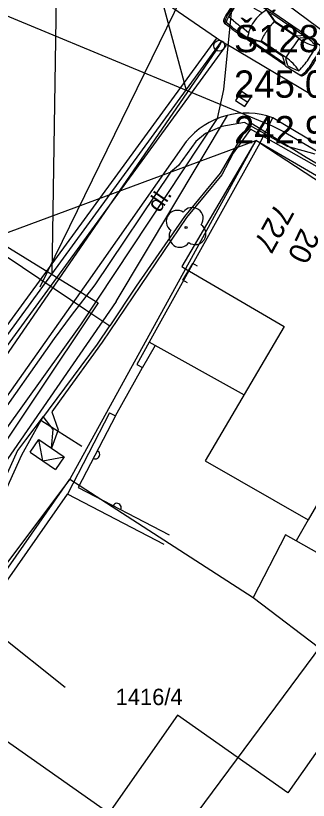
# Model space of a CAD drawing. Extents: x -601580 to 4, y -1204314 to 4.
# Drawn here: x -600325.47 to -600312.05, y -1203714.84 to -1203678.86 of the extents above; entities that cross this region are included whole.
import ezdxf

# ---------------------------------------------------------------- set-up
doc = ezdxf.new("R2010")
doc.units = 0
for name, color, linetype in [('00-EON NN', 7, 'Continuous'), ('00-EON VN', 7, 'Continuous'), ('00-INNOGY-NTL', 7, 'Continuous'), ('00-KN-HRANICE PARCEL', 7, 'Continuous'), ('00-KN-PARC. CISLA', 7, 'Continuous'), ('00-KN-VNITRNI KRESBA', 7, 'Continuous'), ('00-POLOHOPIS', 7, 'Continuous'), ('00-RAZÍTKO', 7, 'Continuous'), ('00-SITE KOM. KABEL', 7, 'Continuous'), ('00-VAK-KANAL-POPIS', 7, 'Continuous'), ('00-VAK-KANAL-POTRUBI', 7, 'Continuous'), ('00-VAK-VODA-RAD IGIS', 7, 'Continuous'), ('00-VODOVOD STAVAJICI', 7, 'Continuous'), ('11-REKONSTRUKCE  VYKOP', 7, 'Continuous'), ('11-REKONSTRUKCE VODOVOD', 7, 'Continuous'), ('11-REKONSTRUKCE VODOVOD POPIS', 7, 'Continuous'), ('1NP -vybaveni', 7, 'Continuous'), ('Vrstva 22', 7, 'Continuous'), ('Vrstva 26', 7, 'Continuous'), ('Vrstva 27', 7, 'Continuous'), ('Vrstva 28', 7, 'Continuous'), ('Vrstva 40', 7, 'Continuous'), ('Vrstva 6', 7, 'Continuous'), ('Vrstva 9', 7, 'Continuous')]:
    doc.layers.add(name, color=color, linetype=linetype)

# ---------------------------------------------------------------- blocks, each defined once
blk = doc.blocks.new('3.13_358')
at = {"layer": 'Vrstva 22'}
blk.add_circle((0, 0), 0.05, dxfattribs=at)
for centre, start, end in [((0, 0.5), 359.9999, 179.9999), ((-0.5, 0), 89.9999, 269.9999), ((0.5, 0), 269.9999, 89.9999), ((0, -0.5), 179.9999, 359.9999)]:
    blk.add_arc(centre, 0.5, start, end, dxfattribs=at)
blk = doc.blocks.new('6.30_262')
at = {"layer": 'Vrstva 27'}
blk.add_line((-0.25, 0), (0.25, 0), dxfattribs=at)
blk.add_lwpolyline([(-0.25, -0.25), (0.25, -0.25), (0.25, 0.25), (-0.25, 0.25)], close=True, dxfattribs=at)
blk = doc.blocks.new('6.14A_572')
at = {"layer": 'Vrstva 28'}
blk.add_circle((0, 0), 0.25, dxfattribs=at)
blk = doc.blocks.new('DL_32')
at = {"layer": 'Vrstva 40'}
blk.add_text('dl.', height=0.75, rotation=360, dxfattribs=at).set_placement((-0.174, -0.375))
blk = doc.blocks.new('VCHOD_2442')
at = {"layer": 'Vrstva 6'}
blk.add_line((0, 0.25), (0, 0), dxfattribs=at)
blk = doc.blocks.new('VCHOD_2444')
at = {"layer": 'Vrstva 6'}
blk.add_line((0, 0.25), (0, 0), dxfattribs=at)
blk = doc.blocks.new('NN630')
at = {"layer": 'Vrstva 9'}
for points in [[(-3, -700), (-703, 0)], [(-703, -700), (-703, 0), (697, 0), (697, -700)], [(-3, -700), (697, 0)], [(-703, -700), (697, -700)]]:
    blk.add_lwpolyline(points, dxfattribs=at)
blk = doc.blocks.new('CA0106H2')
for p, q in [((1.038, 0), (1.038, -0.039)), ((1.038, 0), (2.851, 0)), ((1.95, -0.07), (1.95, 0)), ((2.824, 0.153), (2.878, -0.152)), ((2.874, 0.137), (2.824, 0.153)), ((2.967, -0.12), (2.874, 0.137)), ((2.924, 0), (3.528, 0)), ((0.538, -0.013), (0.17, -0.031)), ((0.902, -0.068), (1.15, -0.271)), ((1.038, -0.039), (1.336, -0.284)), ((2.863, -0.07), (1.075, -0.07)), ((1.197, -0.322), (2.562, -0.322)), ((1.336, -0.284), (2.512, -0.284)), ((2.512, -0.284), (3.106, -0.07)), ((2.558, -0.284), (3.152, -0.07)), ((3.106, -0.07), (2.949, -0.07)), ((3.152, -0.07), (3.533, -0.07)), ((3.245, -0.3), (3.626, -0.321)), ((4.028, -0.013), (4.396, -0.031)), ((4.033, -0.083), (4.364, -0.099)), ((0, -0.848), (0, -0.496)), ((1.194, -0.364), (1.194, -0.848)), ((4.124, -0.362), (4.427, -0.394)), ((4.432, -0.848), (4.432, -0.508)), ((4.57, -0.848), (4.57, -0.508)), ((0, -0.848), (0, -1.199)), ((1.194, -1.331), (1.194, -0.848)), ((4.432, -0.848), (4.432, -1.187)), ((4.57, -0.848), (4.57, -1.187)), ((0.902, -1.627), (1.15, -1.424)), ((1.038, -1.656), (1.336, -1.411)), ((1.197, -1.373), (2.562, -1.373)), ((1.336, -1.411), (2.512, -1.411)), ((2.512, -1.411), (3.106, -1.625)), ((2.558, -1.411), (3.152, -1.625)), ((3.245, -1.395), (3.626, -1.374)), ((4.124, -1.333), (4.427, -1.301)), ((0.538, -1.682), (0.17, -1.664)), ((1.038, -1.695), (1.038, -1.656)), ((1.038, -1.695), (2.851, -1.695)), ((2.863, -1.625), (1.075, -1.625)), ((1.95, -1.625), (1.95, -1.695)), ((2.824, -1.848), (2.878, -1.543)), ((2.967, -1.575), (2.874, -1.832)), ((2.924, -1.695), (3.528, -1.695)), ((3.106, -1.625), (2.949, -1.625)), ((3.152, -1.625), (3.533, -1.625)), ((4.028, -1.682), (4.396, -1.664)), ((4.033, -1.612), (4.364, -1.596)), ((2.874, -1.832), (2.824, -1.848))]:
    blk.add_line(p, q)
for points in [[(0.064, -0.848), (0.064, -0.505)], [(4.508, -0.848), (4.508, -0.508)], [(0.064, -0.848), (0.064, -1.19)], [(4.508, -0.848), (4.508, -1.187)]]:
    blk.add_lwpolyline(points)
for centre, radius, start, end in [((1.038, -10), 10, 90, 92.8655), ((3.528, -10), 10, 87.1345, 90), ((1.215, -0.496), 1.215, 161.5481, 180), ((0.176, -0.151), 0.12, 92.8655, 160.933), ((1.279, -0.505), 1.215, 161.5481, 180), ((0.257, -0.164), 0.138, 89.0794, 161.5481), ((4.17, -0.848), 3.876, 169.8074, 180), ((1.081, -2.75), 2.689, 93.8081, 105.6622), ((1.18, 1.875), 2.197, 247.9492, 270.4514), ((1.074, -0.364), 0.12, 0, 50.6237), ((2.784, -0.284), 0.888, 166.0463, 180), ((2.812, -0.284), 0.888, 166.0463, 180), ((2.858, -0.352), 0.909, 161.9013, 175.6916), ((-1.274, -0.848), 3.876, 360, 8.3716), ((1.563, -0.848), 1.769, 0, 26.07), ((3.533, -10.07), 10, 87.1345, 90), ((3.066, -10.306), 10, 83.9233, 86.7888), ((4.315, -0.167), 0.138, 18.4519, 90.9206), ((4.484, -0.087), 0.12, 158.1675, 197.8029), ((3.217, -0.508), 1.215, 0, 18.4519), ((4.39, -0.151), 0.12, 19.067, 87.1345), ((3.293, -0.508), 1.215, 0, 18.4519), ((3.355, -0.508), 1.215, 0, 19.067), ((4.17, -0.848), 3.876, 180, 190.1926), ((-1.274, -0.848), 3.876, 351.6284, 0), ((1.563, -0.848), 1.769, 333.93, 0), ((1.215, -1.199), 1.215, 180, 198.4519), ((1.279, -1.19), 1.215, 180, 198.4519), ((1.18, -3.57), 2.197, 89.5486, 112.0508), ((1.074, -1.331), 0.12, 309.3763, 0), ((2.784, -1.411), 0.888, 180, 193.9537), ((2.812, -1.411), 0.888, 180, 193.9537), ((2.858, -1.343), 0.909, 184.3084, 198.0987), ((3.066, 8.611), 10, 273.2112, 276.0767), ((3.217, -1.187), 1.215, 341.5481, 0), ((3.293, -1.187), 1.215, 341.5481, 0), ((3.355, -1.187), 1.215, 340.933, 0), ((0.176, -1.544), 0.12, 199.067, 267.1345), ((0.257, -1.531), 0.138, 198.4519, 270.9206), ((1.081, 1.055), 2.689, 254.3378, 266.1919), ((1.038, 8.305), 10, 267.1345, 270), ((3.528, 8.305), 10, 270, 272.8655), ((3.533, 8.375), 10, 270, 272.8655), ((4.315, -1.528), 0.138, 269.0794, 341.5481), ((4.484, -1.608), 0.12, 162.1971, 201.8325), ((4.39, -1.544), 0.12, 272.8655, 340.933)]:
    blk.add_arc(centre, radius, start, end)

msp = doc.modelspace()

# ---------------------------------------------------------------- linework, layer by layer
at = {"layer": '00-EON NN'}
for points in [[(-600300.1, -1203693.14), (-600300.09, -1203692.82), (-600302.356, -1203691.251), (-600303.624, -1203690.511), (-600305.35, -1203689.5), (-600311.54, -1203685.86), (-600314.7, -1203684.06), (-600315.49, -1203685.17), (-600316.007, -1203686.155), (-600317.63, -1203688.11), (-600321.5, -1203693.84), (-600323.385, -1203696.438)], [(-600323.385, -1203696.438), (-600323.817, -1203697.034), (-600323.521, -1203697.85), (-600323.824, -1203698.698), (-600323.753, -1203697.835), (-600324.207, -1203697.234), (-600325.017, -1203698.307)], [(-600325.017, -1203698.307), (-600325.386, -1203698.796), (-600326.82, -1203701.97), (-600328.814, -1203704.512), (-600330.617, -1203706.864), (-600331.49, -1203707.646), (-600333.526, -1203710.518), (-600334.519, -1203712.072), (-600336.22, -1203714.37), (-600337.32, -1203716)]]:
    msp.add_lwpolyline(points, dxfattribs=at)
at = {"layer": '00-EON VN'}
for points in [[(-600352.702, -1203647.788), (-600344.954, -1203653.759), (-600330.827, -1203664.425), (-600321.645, -1203670.963), (-600317.713, -1203673.458), (-600315.791, -1203674.896), (-600315.293, -1203675.777), (-600315.944, -1203682.246), (-600316.226, -1203683.581), (-600322.501, -1203693.042), (-600331.079, -1203704.985), (-600348.911, -1203730.288), (-600354.208, -1203737.743), (-600361.516, -1203748.136), (-600365.138, -1203753.003), (-600368.824, -1203758.254), (-600375.091, -1203769.039), (-600381.398, -1203780.278), (-600382.49, -1203782.6), (-600383.25, -1203783.59)], [(-600311.727, -1203685.219), (-600313.007, -1203684.869), (-600314.967, -1203683.759), (-600316.007, -1203683.949), (-600316.757, -1203684.269), (-600317.207, -1203684.639), (-600317.997, -1203685.729), (-600318.367, -1203686.039), (-600321.837, -1203691.209), (-600322.927, -1203692.609), (-600323.707, -1203693.669), (-600326.587, -1203697.729), (-600333.047, -1203707.069), (-600337.327, -1203713.329), (-600344.497, -1203723.269)]]:
    msp.add_lwpolyline(points, dxfattribs=at)
at = {"layer": '00-INNOGY-NTL'}
for points in [[(-600309.24, -1203678.67), (-600322.08, -1203669.74), (-600324.1, -1203669.99), (-600324.38, -1203670.02), (-600324.57, -1203670.3), (-600329.11, -1203676.87), (-600329.27, -1203677.14), (-600328.72, -1203677.64), (-600328.46, -1203677.78), (-600313.71, -1203683.92), (-600313.19, -1203684.18), (-600311.2, -1203685.34)], [(-600331.63, -1203676.31), (-600333.84, -1203679.52), (-600334.07, -1203679.86), (-600334.63, -1203680.67), (-600332.29, -1203684.08), (-600331.07, -1203685.85), (-600329.31, -1203687.34), (-600321.69, -1203692.03)], [(-600321.69, -1203692.03), (-600330.58, -1203705.33), (-600337.06, -1203714.26), (-600337.47, -1203714.88), (-600341.61, -1203721.03), (-600343.93, -1203724.48), (-600344.29, -1203725.01), (-600352.8, -1203737.19), (-600355.42, -1203740.94), (-600356.36, -1203742.04), (-600356.56, -1203742.28), (-600357.37, -1203743.06), (-600358.82, -1203744.14), (-600359.04, -1203744.31), (-600359.16, -1203744.4), (-600365.08, -1203752.77), (-600365.18, -1203752.95), (-600368.57, -1203759.1), (-600375.05, -1203770.85), (-600375.18, -1203771.08)]]:
    msp.add_lwpolyline(points, dxfattribs=at)
at = {"layer": '00-KN-HRANICE PARCEL'}
for p, q in [((-600305.11, -1203690.04), (-600314.45, -1203684.58)), ((-600322.98, -1203700.12), (-600331.6, -1203711.54)), ((-600322.98, -1203700.12), (-600314.57, -1203705.54)), ((-600314.57, -1203705.54), (-600309.44, -1203709.45))]:
    msp.add_line(p, q, dxfattribs=at)
for points in [[(-600337.24, -1203696.89), (-600330.06, -1203690.37), (-600314.45, -1203684.58)], [(-600314.45, -1203684.58), (-600317.68, -1203690.47), (-600322.98, -1203700.12)], [(-600305.11, -1203690.04), (-600309.03, -1203696.78), (-600312.05, -1203701.98), (-600312.6, -1203702.94), (-600313.09, -1203702.67), (-600314.57, -1203705.54)], [(-600309.44, -1203709.45), (-600312.98, -1203714.49), (-600318.05, -1203710.93), (-600321.19, -1203715.42), (-600329.58, -1203709.54), (-600322.98, -1203700.12)]]:
    msp.add_lwpolyline(points, dxfattribs=at)
at = {"layer": '00-KN-VNITRNI KRESBA'}
for p, q in [((-600314.45, -1203684.58), (-600317.85, -1203690.37)), ((-600317.85, -1203690.37), (-600317.68, -1203690.47)), ((-600317.68, -1203690.47), (-600313.15, -1203693.12)), ((-600313.15, -1203693.12), (-600316.78, -1203699.27)), ((-600316.78, -1203699.27), (-600312.05, -1203701.98)), ((-600310.53, -1203704.12), (-600312.6, -1203702.94))]:
    msp.add_line(p, q, dxfattribs=at)
at = {"layer": '00-POLOHOPIS'}
for p, q in [((-600320.865, -1203691.972), (-600315.749, -1203683.433)), ((-600314.269, -1203684.712), (-600313.676, -1203683.546)), ((-600304.426, -1203689.116), (-600313.676, -1203683.546)), ((-600317.651, -1203684.638), (-600322.148, -1203691.029)), ((-600317.805, -1203690.988), (-600317.344, -1203690.225)), ((-600322.148, -1203691.029), (-600335.017, -1203709.24)), ((-600320.865, -1203691.972), (-600333.392, -1203710.107)), ((-600319.34, -1203693.831), (-600319.918, -1203694.853)), ((-600319.078, -1203693.978), (-600319.656, -1203695)), ((-600314.97, -1203696.261), (-600319.34, -1203693.831)), ((-600320.893, -1203697.211), (-600319.656, -1203695)), ((-600319.918, -1203694.853), (-600319.656, -1203695)), ((-600321.16, -1203697.073), (-600323.1, -1203700.803)), ((-600320.893, -1203697.211), (-600322.602, -1203700.498)), ((-600321.16, -1203697.073), (-600320.893, -1203697.211)), ((-600322.602, -1203700.498), (-600318.433, -1203702.666)), ((-600327.117, -1203706.554), (-600323.1, -1203700.803)), ((-600318.664, -1203703.11), (-600323.1, -1203700.803)), ((-600323.204, -1203709.666), (-600327.117, -1203706.554))]:
    msp.add_line(p, q, dxfattribs=at)
for points in [[(-600307.904, -1203694.856), (-600305.164, -1203690.673), (-600314.269, -1203684.712), (-600319.34, -1203693.831)], [(-600320.893, -1203697.211), (-600322.602, -1203700.498)], [(-600322.602, -1203700.498), (-600318.433, -1203702.666)]]:
    msp.add_lwpolyline(points, dxfattribs=at)
for centre, radius, start, end in [((-600314.897, -1203686.881), 3.551, 69.885, 140.8373), ((-600321.816, -1203698.985), 0.2, 242.5274, 62.5303), ((-600320.828, -1203701.421), 0.2, 332.5228, 152.5257)]:
    msp.add_arc(centre, radius, start, end, dxfattribs=at)
at = {"layer": '00-RAZÍTKO'}
msp.add_lwpolyline([(-600188.969, -1203708.417), (-600246.123, -1203785.417), (-600325.417, -1203726.559), (-600268.263, -1203649.56)], close=True, dxfattribs=at)
at = {"layer": '00-SITE KOM. KABEL'}
for points in [[(-600291.91, -1203697.34), (-600294.89, -1203695.51), (-600296.18, -1203694.98), (-600299.85, -1203692.83), (-600301.61, -1203691.58), (-600303.13, -1203690.66), (-600304.86, -1203689.65), (-600306.01, -1203688.96), (-600312.14, -1203685.36), (-600314.73, -1203683.76), (-600316.09, -1203686.08)], [(-600316.09, -1203686.08), (-600317.72, -1203688.07), (-600319.94, -1203691.26), (-600321.15, -1203693.08)], [(-600329.66, -1203687.89), (-600328.78, -1203687.96), (-600322.25, -1203692.35), (-600321.15, -1203693.08)], [(-600328.78, -1203687.96), (-600322.25, -1203692.35)], [(-600324.32, -1203697.42), (-600321.71, -1203693.92), (-600321.15, -1203693.08)], [(-600324.32, -1203697.42), (-600325.2, -1203699.01), (-600326.63, -1203702.13)], [(-600322.43, -1203698.61), (-600324.32, -1203697.42)]]:
    msp.add_lwpolyline(points, dxfattribs=at)
at = {"layer": '00-VAK-KANAL-POTRUBI'}
msp.add_line((-600356.108, -1203646.172), (-600311.102, -1203679.776), dxfattribs=at)
at = {"layer": '00-VAK-VODA-RAD IGIS'}
for points in [[(-600316.256, -1203679.894), (-600332.434, -1203668.792), (-600354.837, -1203651.734), (-600377.846, -1203634.299)], [(-600316.022, -1203680.054), (-600316.256, -1203679.894)], [(-600316.022, -1203680.054), (-600316.133, -1203680.243)], [(-600315.791, -1203680.191), (-600316.022, -1203680.054)], [(-600236.89, -1203728.365), (-600242.377, -1203724.953), (-600264, -1203711.729), (-600288.949, -1203696.473), (-600297.916, -1203690.812), (-600315.791, -1203680.191)]]:
    msp.add_lwpolyline(points, dxfattribs=at)
at = {"layer": '00-VODOVOD STAVAJICI'}
msp.add_lwpolyline([(-600316.133, -1203680.243), (-600330.382, -1203700.926)], dxfattribs=at)
at = {"layer": '11-REKONSTRUKCE  VYKOP'}
for points in [[(-600335.828, -1203706.693), (-600316.248, -1203679.889)], [(-600336.078, -1203707.985), (-600315.796, -1203680.219)]]:
    msp.add_lwpolyline(points, dxfattribs=at)
at = {"layer": '11-REKONSTRUKCE VODOVOD'}
msp.add_lwpolyline([(-600336.304, -1203707.82), (-600316.022, -1203680.054)], dxfattribs=at)
msp.add_lwpolyline([(-600336.304, -1203707.82), (-600316.022, -1203680.054)], dxfattribs=at)
at = {"layer": '11-REKONSTRUKCE VODOVOD POPIS'}
for p, q in [((-600323.358, -1203661.028), (-600323.815, -1203690.723)), ((-600323.358, -1203661.028), (-600317.649, -1203682.281)), ((-600312.145, -1203666.299), (-600324.357, -1203691.31))]:
    msp.add_line(p, q, dxfattribs=at)

# ---------------------------------------------------------------- block references
at = {"layer": '00-POLOHOPIS'}
msp.add_blockref('6.14A_572', (-600316.133, -1203680.243), dxfattribs=at)
for name, p, xscale, yscale, rotation in [('6.30_262', (-600315.035, -1203682.685), 1.00000252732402, 1.00000252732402, -33.21262608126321), ('DL_32', (-600319.085, -1203687.571), 1.00000054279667, 1.0000005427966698, 55.36478364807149), ('3.13_358', (-600317.653, -1203688.573), 1.00000054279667, 1.0000005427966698, 55.36478364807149), ('VCHOD_2442', (-600317.344, -1203690.225), 0.99999973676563, 0.9999997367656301, -121.14005715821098), ('VCHOD_2444', (-600317.805, -1203690.988), 0.99999973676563, 0.9999997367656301, -121.14005715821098)]:
    msp.add_blockref(name, p, dxfattribs=dict(at, xscale=xscale, yscale=yscale, rotation=rotation))
at = {"layer": '1NP -vybaveni', "rotation": 145.68342222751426}
msp.add_blockref('CA0106H2', (-600312.273, -1203681.722), dxfattribs=at)
at = {"layer": 'Vrstva 26', "xscale": 0.0010000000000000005, "yscale": 0.0010000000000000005, "rotation": -34.76214450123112}
msp.add_blockref('NN630', (-600323.824, -1203698.698), dxfattribs=at)

# ---------------------------------------------------------------- texts
at = {"layer": '00-KN-PARC. CISLA'}
msp.add_text('1416/4', height=0.75, dxfattribs=at).set_placement((-600320.881, -1203710.47))
at = {"layer": '00-POLOHOPIS'}
for s, rotation, p in [('727', 241.0711, (-600313.53, -1203687.397)), ('20', 244.7489, (-600312.387, -1203688.551))]:
    msp.add_text(s, height=1, rotation=rotation, dxfattribs=at).set_placement(p)
at = {"layer": '00-VAK-KANAL-POPIS'}
for s, p in [('Š128', (-600315.454, -1203680.537)), ('245.02', (-600315.454, -1203682.625)), ('242.98', (-600315.454, -1203684.713))]:
    msp.add_text(s, height=1.25, dxfattribs=at).set_placement(p)

doc.saveas('drawing.dxf')
